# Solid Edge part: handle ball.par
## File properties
Title: Handle Ball
Author: Deepak Maini
Template: Normal.par
Last saved by: CADCIM
Revision: 10
Application: Solid Edge
Density: 0.0000078 kg/mm^3
Accuracy: 0.01
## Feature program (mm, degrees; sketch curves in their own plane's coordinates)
sketch for "unnamed RevolvedProtrusion 1" plane through (0, 0, 0) normal (0, -1, 0) x-axis (1, 0, 0)
  arc centre (0, 0) radius 9.525 from (0, 9.525) to (0, -9.525) cw
  line (0, 9.525) -> (0, -9.525)
revolve "unnamed RevolvedProtrusion 1" add finite 360 deg
sketch for "unnamed Cutout 1" plane through (0, 0, 0) normal (0, -1, 0) x-axis (1, 0, 0)
  circle centre (0, 0) radius 3.9751
extrude "unnamed Cutout 1" cut finite 50.8 symmetric
sketch for "ExtrudedCutout_2" plane through (0, 0, 0) normal (0, 0, 1) x-axis (1, 0, 0)
  circle centre (0, 0) radius 1.905
extrude "ExtrudedCutout_2" cut finite 50.8 symmetric
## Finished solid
Body 1: solid body, 4 faces, 6 edges, 0 vertices.
  Faces by surface: cylinder 3, sphere 1
  Edges by curve: circle 4, intersection 2
Bounding box of the edges (mm; curved faces can reach further): 7.950 x 17.312 x 18.665, from (-3.9751, -8.6559, -9.3326) to (3.9751, 8.6559, 9.3326).
Cylindrical faces by radius (mm): R1.905 x2, R3.9751 x1
Spherical faces by radius (mm): R9.525 x1
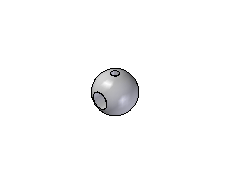
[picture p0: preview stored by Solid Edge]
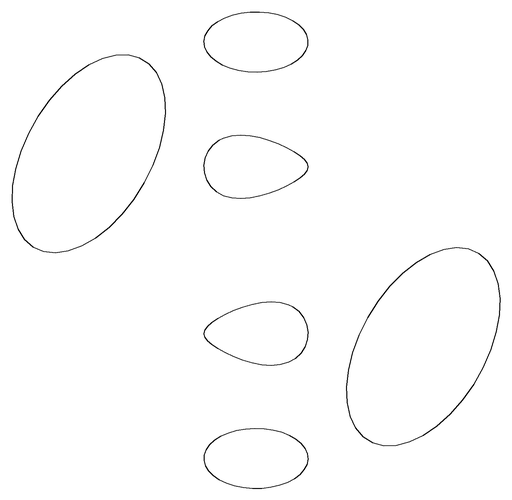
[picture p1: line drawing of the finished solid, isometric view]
